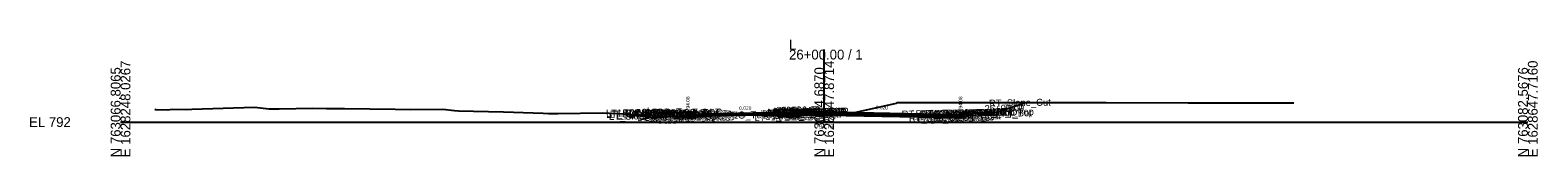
# Model space of a CAD drawing. Extents: x -26 to 4403, y -510 to 9556.
# Drawn here: x 974.3 to 1402.8, y 5990.3 to 6023.4 of the extents above; entities that cross this region are included whole.
import ezdxf

# ---------------------------------------------------------------- set-up
doc = ezdxf.new("R2010")
doc.units = 0
for name, color, linetype in [('Default', 7, 'Continuous'), ('Exist CMT Pavement', 7, 'Continuous'), ('Exist Cross Section Cell', 7, 'Continuous'), ('Exist XS Center Line Elevation Label', 7, 'Continuous'), ('Exist XS Ground Line', 7, 'Continuous'), ('Prop CMT Conc Surface', 7, 'Continuous'), ('Prop CMT Concrete Structures', 7, 'Continuous'), ('Prop CMT Pvmt Course 1', 7, 'Continuous'), ('Prop CMT Pvmt Course 1 CG', 7, 'Continuous'), ('Prop CMT Pvmt Course 1 Wedge', 7, 'Continuous'), ('Prop CMT Pvmt Course 2', 7, 'Continuous'), ('Prop CMT Pvmt Course 2 Wedge', 7, 'Continuous'), ('Prop CMT Pvmt Course 3', 7, 'Continuous'), ('Prop CMT Pvmt Course 3 Wedge', 7, 'Continuous'), ('Prop CMT Pvmt Surface', 7, 'Continuous'), ('Prop CMT Pvmt Wedge Surface 1', 7, 'Continuous'), ('Prop CMT Pvmt Wedge Surface 2', 7, 'Continuous'), ('Prop CMT Pvmt Wedge Surface 3', 7, 'Continuous'), ('Prop CMT Slope Grass', 7, 'Continuous'), ('Prop CMT Subgrade Earthwork', 7, 'Continuous'), ('Prop XS Hydro Elevations', 7, 'Continuous'), ('Prop XS SE Text', 7, 'Continuous'), ('Prop XS Side Slope Text', 7, 'Continuous'), ('Scratch_Level_0', 7, 'Continuous')]:
    doc.layers.add(name, color=color, linetype=linetype)

msp = doc.modelspace()

# ---------------------------------------------------------------- linework, layer by layer
at = {"layer": 'Exist CMT Pavement'}
msp.add_lwpolyline([(1163.27, 6001.85), (1164.07, 6001.88), (1171.19, 6002.16), (1178.03, 6002.03), (1181.29, 6001.97), (1184.93, 6001.83), (1190.8, 6001.62)], dxfattribs=at)
at = {"layer": 'Exist Cross Section Cell'}
for p, q in [((1200, 6000), (1200, 6020.59)), ((1000, 6000), (1200, 6000)), ((1200, 6000), (1400, 6000))]:
    msp.add_line(p, q, dxfattribs=at)
at = {"layer": 'Exist XS Ground Line'}
msp.add_lwpolyline([(1009.77, 6003.63), (1010.07, 6003.55), (1013.44, 6003.53), (1014.67, 6003.63), (1018.81, 6003.62), (1020.25, 6003.66), (1038.04, 6004.25), (1042.21, 6003.74), (1045.05, 6003.74), (1054.65, 6003.95), (1058.58, 6003.91), (1063.68, 6003.85), (1078.07, 6003.65), (1082.47, 6003.54), (1091.61, 6003.66), (1094.92, 6003.26), (1096.07, 6003.16), (1108.87, 6002.88), (1120.08, 6002.57), (1121.65, 6002.42), (1124.36, 6002.49), (1136.94, 6002.64), (1143.09, 6002.31), (1149.3, 6001.69), (1149.71, 6001.35), (1164.07, 6001.88), (1171.19, 6002.16), (1178.03, 6002.03), (1181.29, 6001.97), (1184.93, 6001.83), (1190.8, 6001.62), (1191.9, 6001.51), (1192.67, 6001.44), (1193.24, 6001.88), (1195.66, 6002.26), (1197.05, 6002.45), (1199.44, 6002.79), (1200, 6002.79), (1201.2, 6002.79), (1204.44, 6002.79), (1207.76, 6002.74), (1208.59, 6002.71), (1220.52, 6005.36), (1220.7, 6005.57), (1234.77, 6005.57), (1243.47, 6005.56), (1253.07, 6005.55), (1273.47, 6005.54), (1280.15, 6005.54), (1303.47, 6005.52), (1332.41, 6005.5), (1333.47, 6005.5)], dxfattribs=at)
at = {"layer": 'Prop CMT Conc Surface'}
for points in [[(1156.75, 6002.67), (1151.75, 6002.77)], [(1161.25, 6002.08), (1161.25, 6002.58), (1160.75, 6002.58)], [(1163.25, 6002.2), (1161.25, 6002.08)], [(1236.75, 6002.2), (1238.75, 6002.08)], [(1238.75, 6002.08), (1238.75, 6002.58), (1239.25, 6002.58)], [(1243.43, 6002.68), (1248.43, 6002.78)]]:
    msp.add_lwpolyline(points, dxfattribs=at)
at = {"layer": 'Prop CMT Concrete Structures'}
for points in [[(1151.75, 6002.44), (1151.75, 6002.77)], [(1151.75, 6002.77), (1156.75, 6002.67)], [(1156.75, 6002.34), (1151.75, 6002.44)], [(1156.75, 6002.67), (1156.75, 6002.34)], [(1163.25, 6002.2), (1161.25, 6002.08), (1161.25, 6002.58), (1160.75, 6002.58)], [(1160.75, 6002.58), (1160.75, 6001.57), (1163.25, 6001.62)], [(1163.25, 6001.62), (1163.25, 6002.2)], [(1196, 6003.02), (1195.99, 6003.19), (1195.24, 6003.44), (1194, 6003.46), (1192.76, 6003.2), (1192.01, 6002.95), (1192, 6002.78)], [(1192, 6002.78), (1196, 6003.02)], [(1236.75, 6002.2), (1238.75, 6002.08), (1238.75, 6002.58), (1239.25, 6002.58)], [(1239.25, 6002.58), (1239.25, 6001.57), (1236.75, 6001.62)], [(1236.75, 6001.62), (1236.75, 6002.2)], [(1248.43, 6002.78), (1243.43, 6002.68)], [(1243.43, 6002.68), (1243.43, 6002.34)], [(1243.43, 6002.34), (1248.43, 6002.44)], [(1248.43, 6002.44), (1248.43, 6002.78)]]:
    msp.add_lwpolyline(points, dxfattribs=at)
at = {"layer": 'Prop CMT Pvmt Course 1'}
for points in [[(1192, 6002.78), (1163.25, 6002.2)], [(1163.25, 6002.08), (1192, 6002.65)], [(1163.25, 6002.2), (1163.25, 6001.95), (1163.25, 6001.95), (1163.25, 6002.08)], [(1192, 6002.78), (1196, 6003.02)], [(1192, 6002.53), (1192, 6002.78)], [(1192, 6002.53), (1192, 6002.78)], [(1196, 6002.77), (1192, 6002.53)], [(1192, 6002.65), (1192, 6002.53), (1192, 6002.53)], [(1196, 6003.02), (1196, 6002.77)], [(1196, 6003.02), (1236.75, 6002.2)], [(1196, 6002.77), (1196, 6003.02)], [(1236.75, 6001.95), (1196, 6002.77)], [(1236.75, 6002.2), (1236.75, 6001.95)]]:
    msp.add_lwpolyline(points, dxfattribs=at)
msp.add_lwpolyline([(1196, 6002.77), (1196, 6002.89), (1196, 6002.89), (1196, 6002.77)], close=True, dxfattribs=at)
at = {"layer": 'Prop CMT Pvmt Course 1 CG'}
for points in [[(1163.25, 6001.62), (1160.25, 6001.56), (1159.91, 6001.22)], [(1159.91, 6001.22), (1163.25, 6001.29)], [(1163.25, 6001.29), (1163.25, 6001.62)], [(1236.75, 6001.62), (1239.75, 6001.56), (1240.09, 6001.22)], [(1236.75, 6001.29), (1236.75, 6001.62)], [(1240.09, 6001.22), (1236.75, 6001.29)]]:
    msp.add_lwpolyline(points, dxfattribs=at)
at = {"layer": 'Prop CMT Pvmt Course 1 Wedge'}
for points in [[(1163.25, 6002.08), (1164.07, 6002.1), (1171.19, 6002.24), (1178.03, 6002.37), (1181.29, 6002.44), (1184.93, 6002.51), (1190.8, 6002.63), (1191.9, 6002.65), (1192, 6002.65)], [(1192, 6002.53), (1191.9, 6002.53), (1190.8, 6002.5), (1184.93, 6002.39), (1181.29, 6002.31), (1178.03, 6002.25), (1172.43, 6002.14), (1171.19, 6002.16), (1168.72, 6002.06), (1164.07, 6001.97), (1163.25, 6001.95)], [(1163.25, 6001.95), (1163.25, 6002.08)], [(1192, 6002.65), (1192, 6002.53)]]:
    msp.add_lwpolyline(points, dxfattribs=at)
at = {"layer": 'Prop CMT Pvmt Course 2'}
for points in [[(1163.25, 6001.62), (1163.25, 6001.62), (1163.25, 6001.95), (1163.25, 6001.95)], [(1163.25, 6001.95), (1163.25, 6001.62)], [(1192, 6002.53), (1196, 6002.77)], [(1192, 6002.2), (1192, 6002.53)], [(1196, 6002.44), (1192, 6002.2)], [(1196, 6002.77), (1196, 6002.44)], [(1196, 6002.44), (1196, 6002.77)], [(1196, 6002.77), (1236.75, 6001.95)], [(1236.75, 6001.62), (1196, 6002.44)], [(1236.75, 6001.95), (1236.75, 6001.62)]]:
    msp.add_lwpolyline(points, dxfattribs=at)
at = {"layer": 'Prop CMT Pvmt Course 2 Wedge'}
for points in [[(1163.25, 6001.95), (1164.07, 6001.97), (1168.72, 6002.06)], [(1168.72, 6002.06), (1164.07, 6001.88), (1163.25, 6001.85)], [(1163.25, 6001.85), (1163.25, 6001.95)], [(1172.43, 6002.14), (1178.03, 6002.25)], [(1192, 6002.2), (1191.9, 6002.19), (1190.8, 6002.17), (1184.93, 6002.05), (1181.29, 6001.98), (1180.91, 6001.97), (1178.03, 6002.03), (1172.43, 6002.14)], [(1178.03, 6002.25), (1181.29, 6002.31), (1184.93, 6002.39), (1190.8, 6002.5), (1191.9, 6002.53), (1192, 6002.53)], [(1192, 6002.53), (1192, 6002.2)]]:
    msp.add_lwpolyline(points, dxfattribs=at)
at = {"layer": 'Prop CMT Pvmt Course 3'}
for points in [[(1163.25, 6001.62), (1163.25, 6001.62), (1163.25, 6001.29), (1163.25, 6001.29)], [(1163.25, 6001.29), (1163.25, 6001.62)], [(1192, 6002.2), (1196, 6002.44)], [(1192, 6001.86), (1192, 6002.2)], [(1196, 6002.1), (1192, 6001.86)], [(1196, 6002.44), (1196, 6002.1)], [(1196, 6002.44), (1236.75, 6001.62)], [(1196, 6002.1), (1196, 6002.44)], [(1236.75, 6001.29), (1196, 6002.1)], [(1236.75, 6001.62), (1236.75, 6001.29)]]:
    msp.add_lwpolyline(points, dxfattribs=at)
at = {"layer": 'Prop CMT Pvmt Course 3 Wedge'}
for points in [[(1180.91, 6001.97), (1181.29, 6001.98)], [(1192, 6001.5), (1191.9, 6001.51), (1190.8, 6001.62), (1184.93, 6001.83), (1181.29, 6001.97), (1180.91, 6001.97)], [(1181.29, 6001.98), (1184.93, 6002.05), (1190.8, 6002.17), (1191.9, 6002.19), (1192, 6002.2)]]:
    msp.add_lwpolyline(points, dxfattribs=at)
at = {"layer": 'Prop CMT Pvmt Surface'}
for points in [[(1192, 6002.78), (1163.25, 6002.2)], [(1192, 6002.78), (1196, 6003.02)], [(1196, 6003.02), (1236.75, 6002.2)]]:
    msp.add_lwpolyline(points, dxfattribs=at)
at = {"layer": 'Prop CMT Pvmt Wedge Surface 1'}
for points in [[(1192, 6002.65), (1163.25, 6002.08)], [(1163.25, 6001.95), (1163.25, 6002.2)], [(1163.25, 6002.08), (1163.25, 6001.95), (1163.25, 6001.95)], [(1192, 6002.78), (1192, 6002.53), (1192, 6002.53), (1192, 6002.65)]]:
    msp.add_lwpolyline(points, dxfattribs=at)
at = {"layer": 'Prop CMT Pvmt Wedge Surface 2'}
for points in [[(1192, 6002.53), (1163.25, 6001.95)], [(1163.25, 6001.95), (1163.25, 6002.2)], [(1192, 6002.78), (1192, 6002.53)]]:
    msp.add_lwpolyline(points, dxfattribs=at)
at = {"layer": 'Prop CMT Pvmt Wedge Surface 3'}
for points in [[(1192, 6002.2), (1163.25, 6001.62)], [(1163.25, 6001.62), (1163.25, 6002.2)], [(1192, 6002.78), (1192, 6002.2)]]:
    msp.add_lwpolyline(points, dxfattribs=at)
at = {"layer": 'Prop CMT Slope Grass'}
for points in [[(1248.43, 6002.77), (1248.95, 6002.78), (1257.27, 6005.55)], [(1160.75, 6002.58), (1151.25, 6002.77), (1148.3, 6001.79)], [(1239.25, 6002.58), (1248.43, 6002.77)]]:
    msp.add_lwpolyline(points, dxfattribs=at)
at = {"layer": 'Prop CMT Subgrade Earthwork'}
msp.add_line((1190.8, 6001.84), (1190.8, 6001.62), dxfattribs=at)
for points in [[(1163.25, 6001.29), (1159.91, 6001.22), (1158.5, 6002.63)], [(1163.25, 6001.29), (1163.27, 6001.85)], [(1163.25, 6001.29), (1163.25, 6001.29)], [(1192, 6001.86), (1190.8, 6001.84)], [(1192, 6001.86), (1196, 6002.1)], [(1196, 6002.1), (1236.75, 6001.29)], [(1236.75, 6001.29), (1240.09, 6001.22), (1241.5, 6002.63)]]:
    msp.add_lwpolyline(points, dxfattribs=at)

# ---------------------------------------------------------------- texts
at = {"layer": 'Default'}
msp.add_text('-', height=0.0001, dxfattribs=at).set_placement((1000, 6000))
at = {"layer": 'Exist Cross Section Cell'}
for s, p in [('L', (1190, 6020.59)), ('26+00.00 / 1', (1190, 6017.79)), ('EL 792', (974, 5998.6))]:
    msp.add_text(s, height=2.8, dxfattribs=at).set_placement(p)
for s, p in [('E 1628248.0267', (1002.8, 5990)), ('E 1628447.8714', (1202.8, 5990)), ('E 1628647.7160', (1402.8, 5990)), ('N 763066.8065', (1000, 5990)), ('N 763074.6870', (1200, 5990)), ('N 763082.5676', (1400, 5990))]:
    msp.add_text(s, height=2.8, rotation=90, dxfattribs=at).set_placement(p)
at = {"layer": 'Exist XS Center Line Elevation Label'}
msp.add_text('794.79', height=1.2, dxfattribs=at).set_placement((1197.56, 5998.19))
at = {"layer": 'Prop XS Hydro Elevations'}
for p in [(1161.75, 6003.08), (1239.25, 6003.08)]:
    msp.add_text('794.08', height=1, rotation=90, dxfattribs=at).set_placement(p)
at = {"layer": 'Prop XS SE Text'}
for rotation, p in [(1.1458, (1175.86, 6003.46)), (358.8543, (1214.65, 6003.65))]:
    msp.add_text('0.020', height=1, rotation=rotation, dxfattribs=at).set_placement(p)
at = {"layer": 'Prop XS Side Slope Text'}
for rotation, p in [(18.4333, (1148.79, 6002.74)), (18.4349, (1251.45, 6004.1))]:
    msp.add_text('3:1', height=1, rotation=rotation, dxfattribs=at).set_placement(p)
at = {"layer": 'Scratch_Level_0'}
for s, p in [('LT_SDWK_Out_Top', (1138.01, 6001.5)), ('LT_Sub_Trench_Out_DLT', (1139.09, 6001.24)), ('LT_CSLP_Pnt', (1141.44, 6001.58)), ('26+00.00', (1144.67, 6001.64)), ('LT_SDWK_In_Top', (1144.63, 6001.43)), ('LT_CG_Top_BOC', (1149.05, 6001.35)), ('LT_PV1_IEEOP', (1182.54, 6001.46)), ('LT_PV1_PGL', (1183.8, 6001.61)), ('MI_Face In', (1183.92, 6001.78)), ('26+00.00', (1185.14, 6001.71)), ('RT_PV2_OEEOP', (1185.28, 6001.55)), ('26+00.00', (1185.53, 6001.94)), ('MI_Top In', (1185.63, 6002.05)), ('RT_PV1_OEEOP', (1185.85, 6001.69)), ('RT_PV2_IEEOP', (1185.93, 6001.57)), ('MI_Face Out', (1186.28, 6001.99)), ('MI_Top Out', (1186.49, 6002.26)), ('RT_PV1_IEEOP', (1186.49, 6001.7)), ('RT_PV2_PGL1', (1186.86, 6001.59)), ('MI_Crown', (1187.09, 6002.32)), ('RT_PV2_PGL', (1187.19, 6001.59)), ('MI_Bot Out', (1187.28, 6001.84)), ('26+00.00', (1187.67, 6002.31)), ('RT_PV1_PGL', (1187.75, 6001.85)), ('RT_Sub_Trench_Out_DLT', (1222.04, 6001.24)), ('RT_CG_Top_BOC', (1227.51, 6001.35)), ('RT_SDWK_In_Top', (1231.26, 6001.43)), ('RT_SDWK_Out_Top', (1234.64, 6001.5)), ('RT_Shld_O', (1240.98, 6001.62)), ('26+00.00', (1241.71, 6001.64)), ('CSLP_Pnt', (1241.83, 6001.64)), ('26+00.00', (1245.61, 6002.82)), ('RT_Slope_Cut', (1246.88, 6004.34)), ('LT_SDWK_Out_Bot', (1138.04, 6001.17)), ('LT_Slope_Fill', (1138.85, 6000.6)), ('LT_SDWK_In_Bot', (1144.66, 6001.1)), ('LT_CG1_Shelf_Out', (1146.82, 6000.29)), ('LT_PV_Sub_Tie_Out', (1148.23, 6000.55)), ('LT_CG_Top_Face', (1148.53, 6001.33)), ('LT_CG_Bot_BOC', (1149.09, 6000.34)), ('LT_CG_Top_Gut', (1149.51, 6000.85)), ('LT_Sub_OEOP', (1150.04, 6000.02)), ('LT_Sub_OEOT_CG', (1150.64, 6000.04)), ('LT_PV_OEEOP_EG', (1150.82, 6000.6)), ('26+00.00', (1152.07, 6001.48)), ('LT_Sub_OEEOP', (1152.48, 6000.07)), ('LT_PV2_OEEOP', (1152.58, 6000.74)), ('LT_PV3_OEEOP', (1152.58, 6000.41)), ('LT_PV1_OEEOP', (1153.15, 6000.88)), ('LT_CG_Bot_IE', (1153.19, 6000.42)), ('LT_Sub_OEOT', (1153.35, 6000.09)), ('LT_PV2_OEOT', (1153.45, 6000.76)), ('LT_PV3_OEOT', (1153.45, 6000.42)), ('LT_PV1_OEOT', (1154.01, 6001.02)), ('26+00.00', (1156.94, 6001.08)), ('LT_PV_EG_TestPt', (1164.06, 6000.76)), ('LT_PV_IEEOP_EG', (1180.21, 6000.26)), ('LT_PV2_IEEOP', (1181.98, 6001.33)), ('LT_PV3_IEEOP', (1181.98, 6001)), ('LT_PV2_PGL1', (1182.9, 6001.35)), ('LT_PV3_PGL1', (1182.9, 6001.01)), ('LT_PV2_PGL', (1183.23, 6001.35)), ('LT_PV3_PGL', (1183.23, 6001.02)), ('LT_PV4_PGL', (1183.23, 6000.69)), ('RT_Sub_OEEOP', (1185.19, 6000.89)), ('RT_PV3_OEEOP', (1185.28, 6001.22)), ('RT_PV3_PGL1', (1186.86, 6001.25)), ('RT_PV4_PGL', (1187.19, 6000.93)), ('RT_Sub_OEOT_CG', (1224.1, 6000.03)), ('RT_CG_Top_Face', (1225.99, 6001.33)), ('RT_CG1_Shelf_Out', (1226.28, 6000.29)), ('RT_CG_Bot_IE', (1226.64, 6000.42)), ('RT_Sub_OEOT', (1226.8, 6000.09)), ('RT_PV2_OEOT', (1226.9, 6000.76)), ('RT_PV3_OEOT', (1226.9, 6000.42)), ('RT_CG_Top_Gut', (1226.96, 6000.85)), ('RT_PV1_OEOT', (1227.46, 6001.02)), ('RT_CG_Bot_BOC', (1227.54, 6000.34)), ('RT_Sub_OEOP', (1230.17, 6000.02)), ('26+00.00', (1230.84, 6001.01)), ('RT_SDWK_In_Bot', (1231.29, 6001.1)), ('26+00.00', (1233.8, 6001.47)), ('RT_SDWK_Out_Bot', (1234.67, 6001.17))]:
    msp.add_text(s, height=2, rotation=1.1458, dxfattribs=at).set_placement(p)

doc.saveas('drawing.dxf')
